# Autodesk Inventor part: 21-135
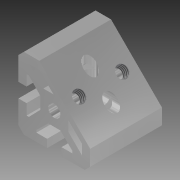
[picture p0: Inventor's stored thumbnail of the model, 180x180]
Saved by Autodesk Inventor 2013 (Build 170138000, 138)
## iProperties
Created: 2004-10
Part Number: 21-135
Material: Aluminium - 6061
Document SubType Name: Modeling
Designer: Autodesk, Inc.
Manufacturer: Standard
Standards Organization: Custom
Description: CORNER ELEMENT 3, 40
Catalog Web Link: http://www.parker.com/ead/cm1.asp?cmid=809
Vendor: PARKER IPS
Mass: 78.2567 g
Surface Area: 142.922 cm^2
Volume: 28.877 cm^3
Density: 2.71 g/cm^3
CAGE: 1LJX3
Dept. ID: Product Design
Description #2: ---
Finish #1: ---
Finish #2: ---
Material ID: ---
Project Number: ---
Author: Autodesk, Inc.
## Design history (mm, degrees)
derived "21-XXX Corner Elements.ipt"
body "Solid1"
tag "TaggingFeature2"
feature "Solid1::21-XXX Corner Elements.ipt" dims "ScaleForDerivedMember" = 10
